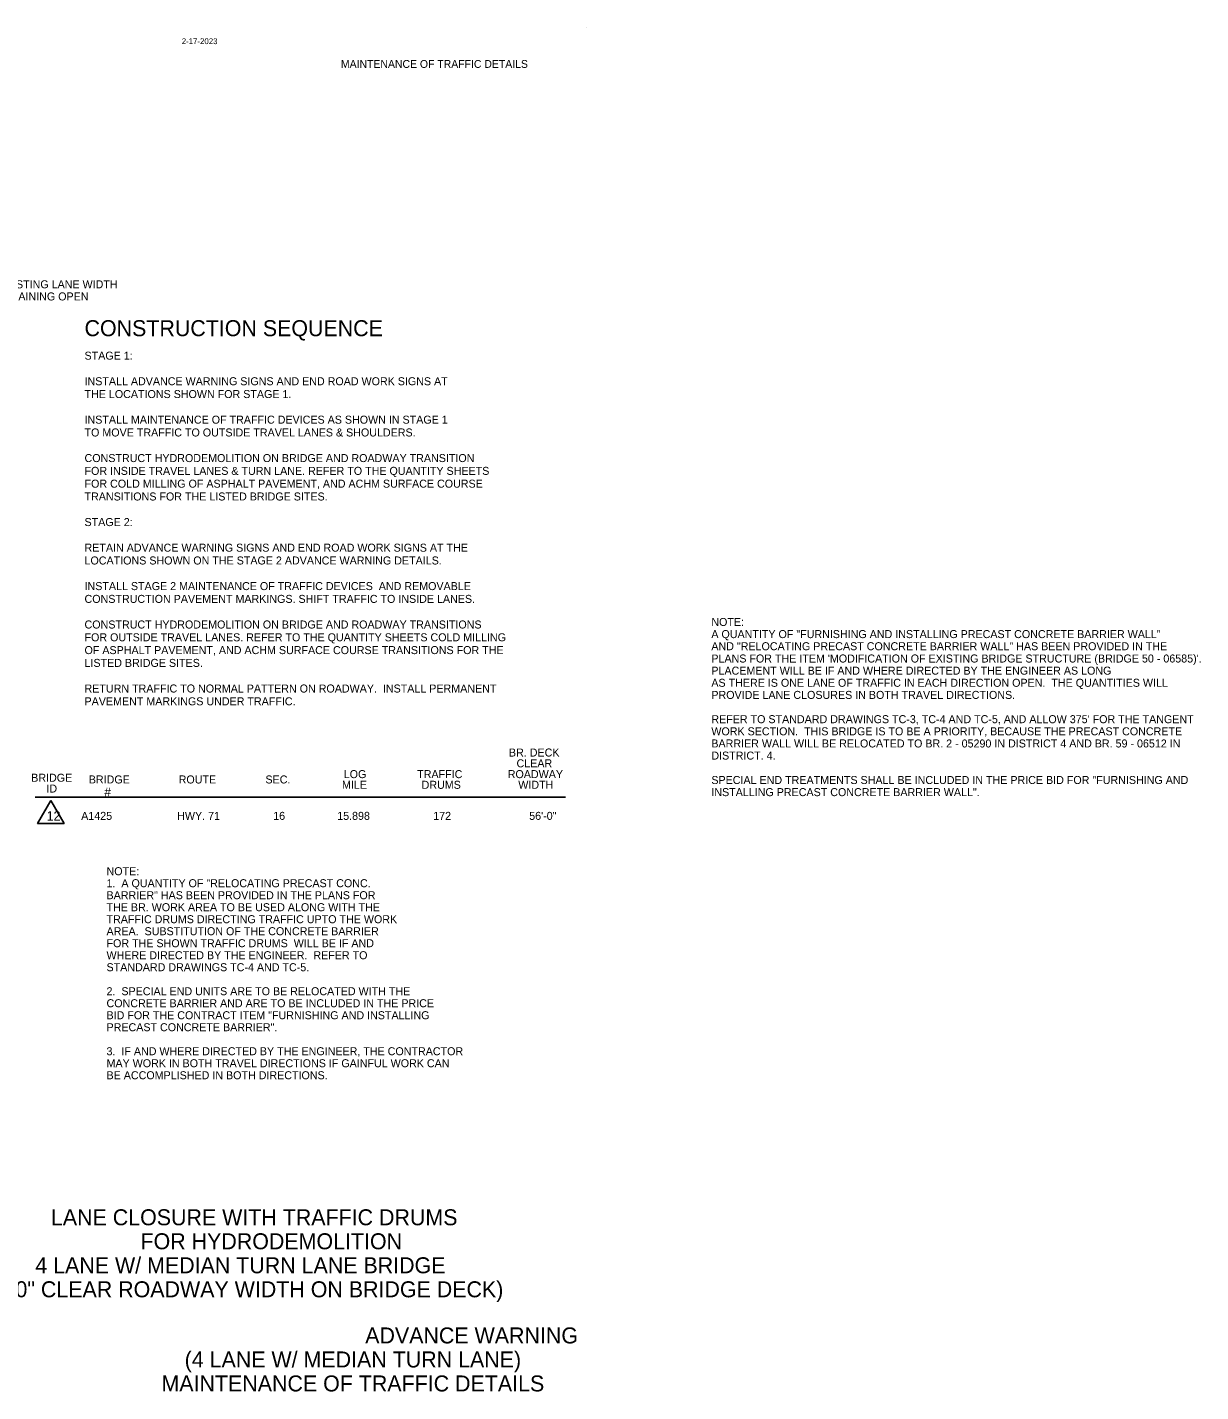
# Model space of a CAD drawing. Extents: x 1930579 to 1938445, y 596452 to 597630.
# Drawn here: x 1937565 to 1938445, y 596607 to 597630 of the extents above; entities that cross this region are included whole.
import ezdxf

# ---------------------------------------------------------------- set-up
doc = ezdxf.new("R2010")
doc.units = 0
for name, color, linetype in [('Default', 7, 'Continuous'), ('R_Border', 7, 'Continuous'), ('R_Border Prem', 7, 'Continuous')]:
    doc.layers.add(name, color=color, linetype=linetype)

msp = doc.modelspace()

# ---------------------------------------------------------------- linework, layer by layer
at = {"layer": 'R_Border'}
msp.add_line((1937570.7, 597052.7), (1937968.3, 597052.7), dxfattribs=at)
msp.add_lwpolyline([(1937582.5, 597050.2), (1937592.4, 597033), (1937572.5, 597033)], close=True, dxfattribs=at)
at = {"layer": 'R_Border Prem'}
msp.add_line((1937984, 597629.9), (1937984, 597629.9), dxfattribs=at)

# ---------------------------------------------------------------- texts
at = {"layer": 'Default'}
for s, p in [('LANE CLOSURE WITH TRAFFIC DRUMS', (1937582.5, 596731.6)), ('FOR HYDRODEMOLITION', (1937649.7, 596713.6)), ('4 LANE W/ MEDIAN TURN LANE BRIDGE', (1937570.8, 596695.6)), ('(56\'-0" CLEAR ROADWAY WIDTH ON BRIDGE DECK)', (1937524.3, 596677.6))]:
    msp.add_text(s, height=12, dxfattribs=at).set_placement(p)
at = {"layer": 'R_Border'}
for s, height, p in [('MAINTAIN EXISTING LANE WIDTH', 6, (1937502.8, 597434.2)), ('ON LANE REMAINING OPEN', 6, (1937502.8, 597425.1)), ('CONSTRUCTION SEQUENCE', 12, (1937607.7, 597398.3)), ('STAGE 1:', 6, (1937607.7, 597380.7)), ('INSTALL ADVANCE WARNING SIGNS AND END ROAD WORK SIGNS AT', 6, (1937607.7, 597361.5)), ('THE LOCATIONS SHOWN FOR STAGE 1.', 6, (1937607.7, 597351.9)), ('INSTALL MAINTENANCE OF TRAFFIC DEVICES AS SHOWN IN STAGE 1', 6, (1937607.7, 597332.7)), ('TO MOVE TRAFFIC TO OUTSIDE TRAVEL LANES & SHOULDERS.', 6, (1937607.7, 597323.1)), ('CONSTRUCT HYDRODEMOLITION ON BRIDGE AND ROADWAY TRANSITION', 6, (1937607.7, 597303.9)), ('FOR INSIDE TRAVEL LANES & TURN LANE. REFER TO THE QUANTITY SHEETS ', 6, (1937607.7, 597294.3)), ('FOR COLD MILLING OF ASPHALT PAVEMENT, AND ACHM SURFACE COURSE ', 6, (1937607.7, 597284.7)), ('TRANSITIONS FOR THE LISTED BRIDGE SITES.', 6, (1937607.7, 597275.1)), ('STAGE 2:', 6, (1937607.7, 597255.9)), ('RETAIN ADVANCE WARNING SIGNS AND END ROAD WORK SIGNS AT THE', 6, (1937607.7, 597236.7)), ('LOCATIONS SHOWN ON THE STAGE 2 ADVANCE WARNING DETAILS.', 6, (1937607.7, 597227.1)), ('INSTALL STAGE 2 MAINTENANCE OF TRAFFIC DEVICES  AND REMOVABLE', 6, (1937607.7, 597207.9)), ('CONSTRUCTION PAVEMENT MARKINGS. SHIFT TRAFFIC TO INSIDE LANES.', 6, (1937607.7, 597198.3)), ('NOTE:', 6, (1938077.8, 597181)), ('CONSTRUCT HYDRODEMOLITION ON BRIDGE AND ROADWAY TRANSITIONS', 6, (1937607.7, 597179.1)), ('A QUANTITY OF "FURNISHING AND INSTALLING PRECAST CONCRETE BARRIER WALL" ', 6, (1938077.8, 597171.9)), ('FOR OUTSIDE TRAVEL LANES. REFER TO THE QUANTITY SHEETS COLD MILLING ', 6, (1937607.7, 597169.5)), ('AND "RELOCATING PRECAST CONCRETE BARRIER WALL" HAS BEEN PROVIDED IN THE ', 6, (1938077.8, 597162.8)), ('OF ASPHALT PAVEMENT, AND ACHM SURFACE COURSE TRANSITIONS FOR THE ', 6, (1937607.7, 597159.9)), ('LISTED BRIDGE SITES.', 6, (1937607.7, 597150.3)), ("PLANS FOR THE ITEM 'MODIFICATION OF EXISTING BRIDGE STRUCTURE (BRIDGE 50 - 06585)'. ", 6, (1938077.8, 597153.6)), ('PLACEMENT WILL BE IF AND WHERE DIRECTED BY THE ENGINEER AS LONG ', 6, (1938077.8, 597144.5)), ('RETURN TRAFFIC TO NORMAL PATTERN ON ROADWAY.  INSTALL PERMANENT', 6, (1937607.7, 597131.1)), ('AS THERE IS ONE LANE OF TRAFFIC IN EACH DIRECTION OPEN.  THE QUANTITIES WILL', 6, (1938077.8, 597135.4)), ('PAVEMENT MARKINGS UNDER TRAFFIC.', 6, (1937607.7, 597121.5)), ('PROVIDE LANE CLOSURES IN BOTH TRAVEL DIRECTIONS.', 6, (1938077.8, 597126.3)), ('WORK SECTION.  THIS BRIDGE IS TO BE A PRIORITY, BECAUSE THE PRECAST CONCRETE ', 6, (1938077.8, 597099)), ("REFER TO STANDARD DRAWINGS TC-3, TC-4 AND TC-5, AND ALLOW 375' FOR THE TANGENT", 6, (1938077.8, 597108.1)), ('BARRIER WALL WILL BE RELOCATED TO BR. 2 - 05290 IN DISTRICT 4 AND BR. 59 - 06512 IN ', 6, (1938077.8, 597089.9)), ('BR. DECK ', 6, (1937926, 597083.1)), ('DISTRICT. 4.', 6, (1938077.8, 597080.8)), ('CLEAR', 6, (1937931.7, 597075)), ('BRIDGE ', 6, (1937567.7, 597064.2)), ('BRIDGE ', 6, (1937610.9, 597062.9)), ('ROUTE', 6, (1937678.3, 597062.9)), ('SEC.', 6, (1937743.4, 597062.9)), ('MILE', 6, (1937800.8, 597058.9)), ('LOG', 6, (1937802.1, 597066.9)), ('TRAFFIC ', 6, (1937857.2, 597066.9)), ('DRUMS', 6, (1937860.5, 597058.9)), ('ROADWAY ', 6, (1937925.1, 597066.9)), ('WIDTH', 6, (1937933, 597058.9)), ('SPECIAL END TREATMENTS SHALL BE INCLUDED IN THE PRICE BID FOR "FURNISHING AND', 6, (1938077.8, 597062.5)), ('ID', 6, (1937579.1, 597056.1)), ('#', 6.71, (1937622.5, 597053)), ('INSTALLING PRECAST CONCRETE BARRIER WALL".', 6, (1938077.8, 597053.4)), ('12', 7, (1937579.3, 597035.1)), ('A1425', 6, (1937605.2, 597035.6)), ('HWY. 71', 6, (1937677.2, 597035.6)), ('16', 6, (1937749.2, 597035.6)), ('15.898', 6, (1937797.2, 597035.6)), ('172', 6, (1937869.2, 597035.6)), ('56\'-0"', 6, (1937941.2, 597035.6)), ('NOTE: ', 6, (1937624.2, 596994.1)), ('1.  A QUANTITY OF "RELOCATING PRECAST CONC.', 6, (1937624.2, 596985.1)), ('BARRIER" HAS BEEN PROVIDED IN THE PLANS FOR ', 6, (1937624.2, 596976.1)), ('THE BR. WORK AREA TO BE USED ALONG WITH THE', 6, (1937624.2, 596967.1)), ('TRAFFIC DRUMS DIRECTING TRAFFIC UPTO THE WORK ', 6, (1937624.2, 596958.1)), ('AREA.  SUBSTITUTION OF THE CONCRETE BARRIER', 6, (1937624.2, 596949.1)), ('FOR THE SHOWN TRAFFIC DRUMS  WILL BE IF AND ', 6, (1937624.2, 596940.1)), ('WHERE DIRECTED BY THE ENGINEER.  REFER TO', 6, (1937624.2, 596931.1)), ('STANDARD DRAWINGS TC-4 AND TC-5.', 6, (1937624.2, 596922.1)), ('2.  SPECIAL END UNITS ARE TO BE RELOCATED WITH THE', 6, (1937624.2, 596904.1)), ('CONCRETE BARRIER AND ARE TO BE INCLUDED IN THE PRICE ', 6, (1937624.2, 596895.1)), ('BID FOR THE CONTRACT ITEM "FURNISHING AND INSTALLING ', 6, (1937624.2, 596886.1)), ('PRECAST CONCRETE BARRIER".', 6, (1937624.2, 596877.1)), ('3.  IF AND WHERE DIRECTED BY THE ENGINEER, THE CONTRACTOR', 6, (1937624.2, 596859.1)), ('MAY WORK IN BOTH TRAVEL DIRECTIONS IF GAINFUL WORK CAN', 6, (1937624.2, 596850.1)), ('BE ACCOMPLISHED IN BOTH DIRECTIONS.', 6, (1937624.2, 596841.1)), ('ADVANCE WARNING ', 12, (1937818.2, 596643)), ('(4 LANE W/ MEDIAN TURN LANE)', 12, (1937682.8, 596625)), ('MAINTENANCE OF TRAFFIC DETAILS', 12, (1937665.4, 596607))]:
    msp.add_text(s, height=height, rotation=360, dxfattribs=at).set_placement(p)
at = {"layer": 'R_Border Prem'}
msp.add_text('2-17-2023', height=4.4, dxfattribs=at).set_placement((1937680.6, 597617.3))
msp.add_text('MAINTENANCE OF TRAFFIC DETAILS', height=5.862, rotation=360, dxfattribs=at).set_placement((1937800, 597599.5))

doc.saveas('drawing.dxf')
